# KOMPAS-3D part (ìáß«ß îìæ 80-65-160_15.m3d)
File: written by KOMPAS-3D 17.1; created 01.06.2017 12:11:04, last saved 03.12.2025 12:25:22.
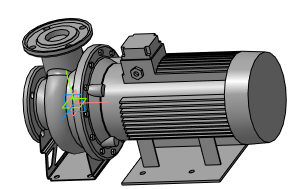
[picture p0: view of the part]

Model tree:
1. Операция без истории:4

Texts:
  ООО АДЛ ГРУПП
